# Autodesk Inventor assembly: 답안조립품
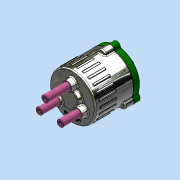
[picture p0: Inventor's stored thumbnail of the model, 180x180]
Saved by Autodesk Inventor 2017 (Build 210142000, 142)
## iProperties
Part Number: 답안조립품
Material: 일반
Document SubType Name: Assembly
Designer: MRC
Mass: 1928.46 g
Surface Area: 1884.94 cm^2
Volume: 517.817 cm^3
Density: 3.72421 g/cm^3
Author: MRC
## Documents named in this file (15)
- C:\Users\MRC\Desktop\620811V1008\답안조립품.iam
- C:\Users\MRC\Desktop\620811V1008\본체.ipt
- C:\Users\MRC\Desktop\620811V1008\메인 축.ipt
- C:\Users\MRC\Desktop\620811V1008\베어링 NA 4900.ipt
- C:\Users\MRC\Desktop\620811V1008\볼트 M5.ipt
- C:\Users\MRC\Desktop\620811V1008\슬라이드 축.ipt
- C:\Users\MRC\Desktop\620811V1008\오일 실.ipt
- C:\Users\MRC\Desktop\620811V1008\커버.ipt
- C:\Users\MRC\Desktop\620811V1008\판캠.ipt
- C:\Users\MRC\Desktop\620811V1008\가변스프링1.ipt
- C:\Users\MRC\Desktop\620811V1008\가변스프링2.ipt
- C:\Users\MRC\Desktop\620811V1008\가변스프링3.ipt
- C:\Users\MRC\Desktop\620811V1008\개스킷.ipt
- C:\Users\MRC\Desktop\620811V1008\멈춤링 10x1.ipt
- C:\Users\MRC\Desktop\620811V1008\멈춤링 22x1.2.ipt
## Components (4 placed, 4 different names)
1. 개스킷:1
2. 가변스프링1:1
3. 가변스프링2:1
4. 가변스프링3:1
